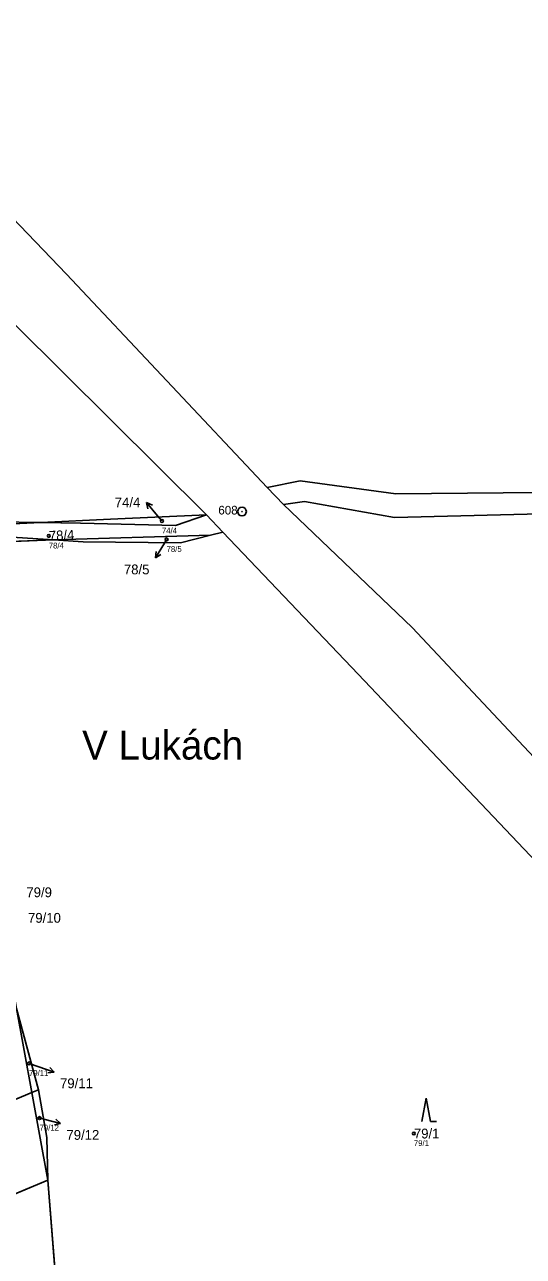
# Model space of a CAD drawing. Extents: x -734504 to -730695, y -1027923 to -1024502.
# Drawn here: x -731979.6 to -731893.3, y -1025821.1 to -1025608 of the extents above; entities that cross this region are included whole.
import ezdxf

# ---------------------------------------------------------------- set-up
doc = ezdxf.new("R2010")
doc.units = 0
for name, color, linetype in [('Definiční body', 7, 'Continuous'), ('Hranice parcel', 7, 'Continuous'), ('Parcelní čísla', 7, 'Continuous'), ('Polygon parcely', 7, 'Continuous'), ('Pop  PČ popisy', 7, 'Continuous'), ('Značky bodu BP', 7, 'Continuous'), ('Značky kultur', 7, 'Continuous')]:
    doc.layers.add(name, color=color, linetype=linetype)

msp = doc.modelspace()

# ---------------------------------------------------------------- linework, layer by layer
at = {"layer": 'Definiční body'}
for centre in [(-731955.82, -1025693.85), (-731975.4, -1025696.44), (-731955.01, -1025697.04), (-731978.82, -1025787.68), (-731976.99, -1025797.14), (-731912.23, -1025799.81)]:
    msp.add_circle(centre, 0.25, dxfattribs=at)
at = {"layer": 'Hranice parcel'}
for p, q in [((-731937.61, -1025688.03), (-731934.8, -1025690.98)), ((-731995.01, -1025694.99), (-731976.76, -1025694.11)), ((-731948.14, -1025692.78), (-731945.31, -1025695.77)), ((-731974.6, -1025697.11), (-731947.44, -1025696.31)), ((-731945.31, -1025695.77), (-731947.44, -1025696.31)), ((-731974.6, -1025697.11), (-732009.17, -1025698.45)), ((-731978.35, -1025792.69), (-731980.98, -1025778.18)), ((-731980.98, -1025778.18), (-731977.2, -1025792.23)), ((-731978.35, -1025792.69), (-731977.2, -1025792.23)), ((-732035.91, -1025816.89), (-731978.35, -1025792.69)), ((-731975.59, -1025807.89), (-731978.35, -1025792.69)), ((-731975.59, -1025807.89), (-732020.18, -1025826.56)), ((-731972.03, -1025852.49), (-731975.59, -1025807.89))]:
    msp.add_line(p, q, dxfattribs=at)
for points in [[(-732041.16, -1025583.36), (-732040.38, -1025583.99), (-732019.29, -1025602.22), (-731972.33, -1025651.13), (-731937.61, -1025688.03)], [(-732047.81, -1025591.16), (-732029.77, -1025610.65), (-731981.22, -1025659.91), (-731948.14, -1025692.78)], [(-732065.24, -1025624.18), (-732045.34, -1025635.68), (-732033.9, -1025649.45), (-732027.79, -1025661.01), (-732014.7, -1025679.14), (-732007.36, -1025686.81), (-732000.19, -1025690.88), (-731984.4, -1025694.01), (-731976.76, -1025694.11)], [(-731937.61, -1025688.03), (-731931.88, -1025686.89), (-731915.37, -1025689.16), (-731884.35, -1025688.88), (-731831.6, -1025686.95), (-731791.85, -1025687.47), (-731750, -1025685.94)], [(-731934.8, -1025690.98), (-731931.15, -1025690.5), (-731915.56, -1025693.26), (-731885.75, -1025692.52), (-731831.14, -1025690.83), (-731791.92, -1025691.23), (-731750.76, -1025690.25)], [(-731934.8, -1025690.98), (-731912.51, -1025712.26), (-731878.29, -1025748.77), (-731835.52, -1025793.53), (-731758.5, -1025874.48), (-731755.36, -1025882.9), (-731754.03, -1025899.12), (-731754, -1025910.04)], [(-731976.76, -1025694.11), (-731969.89, -1025694.2), (-731953.49, -1025694.62), (-731948.14, -1025692.78)], [(-731976.76, -1025694.11), (-731964.72, -1025693.53), (-731948.14, -1025692.78)], [(-731995.01, -1025694.99), (-731990.78, -1025696.08), (-731974.6, -1025697.11)], [(-731947.44, -1025696.31), (-731952.62, -1025697.62), (-731969.43, -1025697.44), (-731974.6, -1025697.11)], [(-731945.31, -1025695.77), (-731921.87, -1025720.35), (-731886.8, -1025757.33), (-731844.36, -1025800.63), (-731772.56, -1025874.06), (-731768.62, -1025885.84), (-731767.6, -1025892.15), (-731769.53, -1025906.54), (-731767.72, -1025909.1)], [(-731977.2, -1025792.23), (-731975.72, -1025800.5), (-731975.59, -1025807.89)]]:
    msp.add_lwpolyline(points, dxfattribs=at)
at = {"layer": 'Polygon parcely'}
for points in [[(-731876.49, -1025346.25), (-731896.77, -1025364.25), (-731910.23, -1025376.07), (-731927.55, -1025398.24), (-731945.89, -1025423.93), (-731959.16, -1025440.96), (-731979.84, -1025475.56), (-732006.37, -1025525.54), (-732038.6, -1025579.81), (-732041.16, -1025583.36), (-732040.38, -1025583.99), (-732019.29, -1025602.22), (-731972.33, -1025651.13), (-731937.61, -1025688.03), (-731931.88, -1025686.89), (-731915.37, -1025689.16), (-731884.35, -1025688.88)], [(-731878.29, -1025748.77), (-731912.51, -1025712.26), (-731934.8, -1025690.98), (-731937.61, -1025688.03), (-731972.33, -1025651.13), (-732019.29, -1025602.22), (-732040.38, -1025583.99), (-732041.16, -1025583.36), (-732042, -1025584.22), (-732045.69, -1025588.63), (-732046.44, -1025589.56), (-732047.81, -1025591.16), (-732029.77, -1025610.65), (-731981.22, -1025659.91), (-731948.14, -1025692.78), (-731945.31, -1025695.77), (-731921.87, -1025720.35), (-731886.8, -1025757.33)], [(-731886.8, -1025757.33), (-731921.87, -1025720.35), (-731945.31, -1025695.77), (-731947.44, -1025696.31), (-731952.62, -1025697.62), (-731969.43, -1025697.44), (-731974.6, -1025697.11), (-732009.17, -1025698.45), (-732007.19, -1025706.28), (-731999.51, -1025718.31), (-731994.44, -1025728.82), (-731987.37, -1025742.89), (-731984.96, -1025756.17), (-731983.17, -1025761.09), (-731982.62, -1025769.1), (-731980.98, -1025778.18), (-731977.2, -1025792.23), (-731975.72, -1025800.5), (-731975.59, -1025807.89), (-731972.03, -1025852.49), (-731921.24, -1025870.32), (-731873.87, -1025886.45)]]:
    msp.add_lwpolyline(points, dxfattribs=at)
for points in [[(-732027.79, -1025661.01), (-732014.7, -1025679.14), (-732007.36, -1025686.81), (-732000.19, -1025690.88), (-731984.4, -1025694.01), (-731976.76, -1025694.11), (-731964.72, -1025693.53), (-731948.14, -1025692.78), (-731981.22, -1025659.91), (-732029.77, -1025610.65), (-732047.81, -1025591.16), (-732055.06, -1025606.24), (-732065.24, -1025624.18), (-732045.34, -1025635.68), (-732033.9, -1025649.45)], [(-732002.5, -1025693.06), (-731995.01, -1025694.99), (-731976.76, -1025694.11), (-731984.4, -1025694.01), (-732000.19, -1025690.88), (-732007.36, -1025686.81), (-732014.7, -1025679.14), (-732027.79, -1025661.01), (-732033.9, -1025649.45), (-732045.34, -1025635.68), (-732065.24, -1025624.18), (-732066.14, -1025625.77), (-732046.85, -1025638.28), (-732036.55, -1025650.85), (-732030.44, -1025662.41), (-732027.53, -1025666.74), (-732016.24, -1025681.55), (-732009.27, -1025689.3)], [(-731931.15, -1025690.5), (-731915.56, -1025693.26), (-731885.75, -1025692.52), (-731831.14, -1025690.83), (-731791.92, -1025691.23), (-731750.76, -1025690.25), (-731750, -1025685.94), (-731791.85, -1025687.47), (-731831.6, -1025686.95), (-731884.35, -1025688.88), (-731915.37, -1025689.16), (-731931.88, -1025686.89), (-731937.61, -1025688.03), (-731934.8, -1025690.98)], [(-731934.8, -1025690.98), (-731912.51, -1025712.26), (-731878.29, -1025748.77), (-731835.52, -1025793.53), (-731758.5, -1025874.48), (-731755.36, -1025882.9), (-731754.03, -1025899.12), (-731754, -1025910.04), (-731749.27, -1025910.38), (-731746.4, -1025904.1), (-731743.69, -1025898.64), (-731743.3, -1025876.3), (-731746.68, -1025785.13), (-731749.5, -1025727.6), (-731750.76, -1025690.25), (-731791.92, -1025691.23), (-731831.14, -1025690.83), (-731885.75, -1025692.52), (-731915.56, -1025693.26), (-731931.15, -1025690.5)], [(-731990.78, -1025696.08), (-731974.6, -1025697.11), (-731947.44, -1025696.31), (-731945.31, -1025695.77), (-731948.14, -1025692.78), (-731953.49, -1025694.62), (-731969.89, -1025694.2), (-731976.76, -1025694.11), (-731995.01, -1025694.99)], [(-731953.49, -1025694.62), (-731948.14, -1025692.78), (-731964.72, -1025693.53), (-731976.76, -1025694.11), (-731969.89, -1025694.2)], [(-732009.17, -1025698.45), (-731974.6, -1025697.11), (-731990.78, -1025696.08), (-731995.01, -1025694.99), (-732010.82, -1025695.75)], [(-731974.6, -1025697.11), (-731969.43, -1025697.44), (-731952.62, -1025697.62), (-731947.44, -1025696.31)], [(-731978.35, -1025792.69), (-731980.98, -1025778.18), (-732037.24, -1025810.89), (-732035.91, -1025816.89)], [(-731977.2, -1025792.23), (-731980.98, -1025778.18), (-731978.35, -1025792.69)], [(-731975.59, -1025807.89), (-731975.72, -1025800.5), (-731977.2, -1025792.23), (-731978.35, -1025792.69)], [(-731975.59, -1025807.89), (-731978.35, -1025792.69), (-732035.91, -1025816.89), (-732035.6, -1025818.19), (-732020.18, -1025826.56)], [(-731975.59, -1025807.89), (-732020.18, -1025826.56), (-732002.22, -1025837.4), (-731972.03, -1025852.49)]]:
    msp.add_lwpolyline(points, close=True, dxfattribs=at)
at = {"layer": 'Pop  PČ popisy'}
for p, q in [((-731956.58, -1025692.94), (-731958.51, -1025690.64)), ((-731958.51, -1025690.64), (-731957.48, -1025691.09)), ((-731958.51, -1025690.64), (-731958.25, -1025691.73)), ((-731955.82, -1025693.85), (-731956.58, -1025692.94)), ((-731955.39, -1025697.68), (-731956.94, -1025700.25)), ((-731955.01, -1025697.04), (-731955.39, -1025697.68)), ((-731956.94, -1025700.25), (-731956.85, -1025699.14)), ((-731956.94, -1025700.25), (-731955.99, -1025699.65)), ((-731978.82, -1025787.68), (-731977.3, -1025788.19)), ((-731977.3, -1025788.19), (-731974.46, -1025789.17)), ((-731974.46, -1025789.17), (-731975.57, -1025789.31)), ((-731974.46, -1025789.17), (-731975.25, -1025788.37)), ((-731976.99, -1025797.14), (-731976.26, -1025797.33)), ((-731976.26, -1025797.33), (-731973.35, -1025798.06)), ((-731973.35, -1025798.06), (-731974.44, -1025798.3)), ((-731973.35, -1025798.06), (-731974.2, -1025797.33))]:
    msp.add_line(p, q, dxfattribs=at)
at = {"layer": 'Značky bodu BP'}
for radius in [0.75, 0.03]:
    msp.add_circle((-731941.97, -1025692.23), radius, dxfattribs=at)
at = {"layer": 'Značky kultur'}
for p, q in [((-731910.08, -1025793.71), (-731910.83, -1025797.71)), ((-731909.33, -1025797.71), (-731910.08, -1025793.71)), ((-731909.33, -1025797.71), (-731908.33, -1025797.71))]:
    msp.add_line(p, q, dxfattribs=at)

# ---------------------------------------------------------------- texts
at = {"layer": 'Definiční body'}
for s, p in [('74/4', (-731955.82, -1025696.01)), ('78/4', (-731975.4, -1025698.6)), ('78/5', (-731955.01, -1025699.2)), ('79/11', (-731978.82, -1025789.84)), ('79/12', (-731976.99, -1025799.3)), ('79/1', (-731912.23, -1025801.97))]:
    msp.add_text(s, height=1, dxfattribs=at).set_placement(p)
at = {"layer": 'Parcelní čísla'}
for s, p in [('74/4', (-731963.99, -1025691.49)), ('78/5', (-731962.41, -1025703.08)), ('79/9', (-731979.28, -1025758.93)), ('79/10', (-731979, -1025763.35)), ('79/11', (-731973.46, -1025791.97)), ('79/1', (-731912.23, -1025800.66)), ('79/12', (-731972.35, -1025800.9))]:
    msp.add_text(s, height=1.7, dxfattribs=at).set_placement(p)
msp.add_text('78/4', height=1.7, rotation=3, dxfattribs=at).set_placement((-731975.35, -1025697.29))
at = {"layer": 'Pop  PČ popisy'}
msp.add_text('V Lukách', height=5, dxfattribs=at).set_placement((-731969.64, -1025735.11))
at = {"layer": 'Značky bodu BP'}
msp.add_text('608', height=1.5, dxfattribs=at).set_placement((-731946.07, -1025692.73))

doc.saveas('drawing.dxf')
